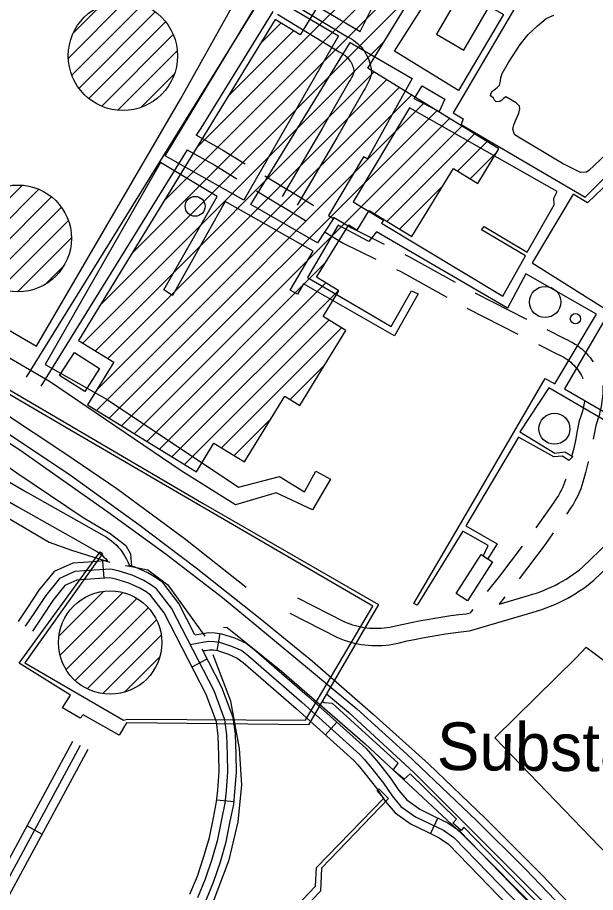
# Model space of a CAD drawing. Extents: x 3568792 to 3606828, y 529143 to 554785.
# Drawn here: x 3577651 to 3578658, y 544184 to 545708 of the extents above; entities that cross this region are included whole.
import ezdxf

# ---------------------------------------------------------------- set-up
doc = ezdxf.new("R2010")
doc.units = 0
for name, color, linetype in [('V-BLDG-OTLN', 7, 'Continuous'), ('V-DOMW-TANK', 7, 'Continuous'), ('V-RAIL-TRAK', 7, 'Continuous'), ('V-ROAD-CNTR', 7, 'Continuous'), ('V-SITE-OTLN', 7, 'Continuous'), ('V-SITE-OTLN-IDEN', 7, 'Continuous'), ('V-TOPO-SHOR', 7, 'Continuous'), ('V-UTIL-LINE', 7, 'Continuous')]:
    doc.layers.add(name, color=color, linetype=linetype)

msp = doc.modelspace()

# ---------------------------------------------------------------- linework, layer by layer
at = {"layer": 'V-BLDG-OTLN'}
for points in [[(3578100.3, 545703.9), (3577757.5, 545145.3), (3577819.1, 545107.6), (3577773.2, 545032.8), (3577962.9, 544916.4), (3577993.6, 544966.4), (3578047, 544933.6), (3578117.2, 545048), (3578143, 545032.1), (3578223.2, 545162.7), (3578183.8, 545186.8), (3578211.4, 545231.7), (3578172.5, 545255.6), (3578228.4, 545346.6), (3578243.2, 545337.5), (3578264, 545371.5), (3578338.1, 545326.1), (3578410.9, 545444.6), (3578453.3, 545418.6), (3578490.2, 545478.8), (3578261.4, 545619.2), (3578452.2, 545930.2), (3578340.8, 545998.6), (3578143.7, 545677.3)], [(3578479.1, 545846.8), (3578381.5, 545678.6), (3578429.2, 545650.9), (3578526.8, 545819.1)], [(3577750.3, 545124.4), (3577794.2, 545096.6), (3577768.6, 545056.2), (3577724.7, 545084)], [(3578478.9, 544759.6), (3578435.2, 544691.8), (3578415.8, 544704.3), (3578459.4, 544772.1)]]:
    msp.add_lwpolyline(points, close=True, dxfattribs=at)
for points in [[(3577962.8, 545479.9), (3578428, 545945.1)], [(3577906.7, 545388.4), (3578449.9, 545931.6)], [(3577850.5, 545296.9), (3578402.2, 545848.6)], [(3577794.4, 545205.4), (3578346, 545757.1)], [(3578075.1, 545662.9), (3578110.1, 545697.9)], [(3578018.9, 545571.4), (3578132, 545684.4)], [(3577765.1, 545140.7), (3578289.9, 545665.6)], [(3577787, 545127.3), (3578272.3, 545612.6)], [(3577808.9, 545113.8), (3578294.2, 545599.1)], [(3577789, 545058.6), (3578316.1, 545585.7)], [(3577788.9, 545023.2), (3578338, 545572.2)], [(3577810.8, 545009.7), (3578359.9, 545558.8)], [(3577832.7, 544996.3), (3578381.8, 545545.3)], [(3577854.7, 544982.8), (3578403.7, 545531.9)], [(3578273.1, 545365.9), (3578425.6, 545518.5)], [(3578295, 545352.5), (3578447.5, 545505)], [(3578418.1, 545440.2), (3578469.5, 545491.6)], [(3578440, 545426.8), (3578487.4, 545474.1)], [(3578316.9, 545339.1), (3578392.5, 545414.6)], [(3577876.6, 544969.4), (3578188.1, 545280.9)], [(3577898.5, 544956), (3578188.4, 545245.8)], [(3577920.4, 544942.5), (3578210.3, 545232.4)], [(3577942.3, 544929.1), (3578193.9, 545180.6)], [(3578006.8, 544958.2), (3578215.8, 545167.2)], [(3578126.3, 545042.4), (3578185.9, 545102)], [(3578028.7, 544944.8), (3578093.7, 545009.8)]]:
    msp.add_lwpolyline(points, dxfattribs=at)
at = {"layer": 'V-DOMW-TANK'}
for p, q in [((3577740.1, 545636.9), (3577839.1, 545735.9)), ((3577746, 545607.5), (3577868.4, 545729.8)), ((3577748.6, 545680.8), (3577794.8, 545727)), ((3577758.5, 545584.6), (3577891.3, 545717.4)), ((3577775.8, 545566.5), (3577909.4, 545700.1)), ((3577797.9, 545553.3), (3577922.5, 545677.9)), ((3577826.2, 545546.3), (3577929.7, 545649.7)), ((3577866.6, 545551.3), (3577924.7, 545609.4)), ((3577559.6, 545315), (3577660.1, 545415.5)), ((3577566.7, 545286.7), (3577688.5, 545408.5)), ((3577579.8, 545264.5), (3577710.6, 545395.3)), ((3577598.1, 545247.4), (3577727.6, 545377)), ((3577621.4, 545235.4), (3577739.7, 545353.7)), ((3577651.4, 545230), (3577745.1, 545323.8)), ((3577700.2, 545243.5), (3577731.8, 545275.1)), ((3577723.7, 544630.6), (3577801.2, 544708.1)), ((3577725.6, 544597.1), (3577834.5, 544706)), ((3577736, 544572.2), (3577859.4, 544695.6)), ((3577751.9, 544552.7), (3577878.9, 544679.7)), ((3577772.9, 544538.3), (3577893.2, 544658.7)), ((3577799.9, 544530), (3577901.6, 544631.7)), ((3577837.9, 544532.6), (3577898.8, 544593.6))]:
    msp.add_line(p, q, dxfattribs=at)
for centre, radius in [((3577834.9, 545640.9), 95.2), ((3577652.2, 545322.9), 93), ((3577960.7, 545378.8), 17.3), ((3578570.6, 545212.1), 27.2), ((3578623.4, 545183.1), 8.92), ((3578586.9, 544991.3), 27), ((3577812.7, 544619), 90)]:
    msp.add_circle(centre, radius, dxfattribs=at)
at = {"layer": 'V-RAIL-TRAK'}
for points in [[(3576442.5, 545653.1), (3576566.5, 545591.5), (3576666.9, 545539.9), (3576763.3, 545491), (3576857.8, 545440.8), (3576956.5, 545388.7), (3577025.7, 545352.9), (3577107.2, 545310.4), (3577213, 545254.2), (3577307.1, 545203.1), (3577446, 545125.3), (3577537.4, 545075.5), (3577625.1, 545020.7), (3577733.7, 544948.8), (3577824.2, 544887.2), (3577944.1, 544799), (3578049.9, 544715.7)], [(3576949.8, 545377.1), (3577053.4, 545322.8), (3577102.6, 545296.8), (3577193.7, 545248.6), (3577322.1, 545177.5), (3577447, 545102.9), (3577541.1, 545044.9), (3577633.4, 544984.3), (3577743.3, 544910.5), (3577862.7, 544824.6), (3577962.7, 544749.4), (3578074, 544660.7), (3578165.3, 544586.5), (3578271.2, 544494.2), (3578367.5, 544407.8), (3578466.6, 544312.8), (3578565.7, 544214.1), (3578656.6, 544118.2)], [(3577102.6, 545296.8), (3577189.6, 545239), (3577285.8, 545181.3), (3577366.5, 545134.1), (3577454.4, 545082.3), (3577555.7, 545018.6), (3577655.5, 544954.4), (3577808.5, 544846.7), (3577910.2, 544773), (3578008.7, 544697.3), (3578071.9, 544645.1), (3578159.9, 544572.2), (3578242.4, 544503.5), (3578329.8, 544424.7), (3578451.2, 544308.8), (3578536.4, 544224.4), (3578627.1, 544129.6)]]:
    msp.add_lwpolyline(points, dxfattribs=at)
at = {"layer": 'V-ROAD-CNTR'}
for p, q in [((3577802.4, 544731.1), (3577800, 544761)), ((3578500.5, 544698.4), (3578490.4, 544685.9)), ((3578444.4, 544676.6), (3578439.8, 544671)), ((3578004, 544634.6), (3577998.7, 544605)), ((3577955.3, 544576.7), (3577981.9, 544590.4)), ((3578207.6, 544480.3), (3578187.5, 544458)), ((3577998.6, 544345), (3578028.4, 544341.9)), ((3578383.6, 544313.5), (3578370.7, 544286.4)), ((3577667.8, 544299.7), (3577694.2, 544285.5))]:
    msp.add_line(p, q, dxfattribs=at)
for points in [[(3578119.5, 545738.8), (3578226.4, 545674.1), (3578229.3, 545672.6), (3578233.1, 545670.4), (3578236.8, 545668), (3578240.3, 545665.4), (3578243.6, 545662.5), (3578246.8, 545659.5), (3578249.8, 545656.3), (3578252.5, 545652.9), (3578255.1, 545649.4), (3578257.5, 545645.7), (3578259.6, 545641.9), (3578261.5, 545638), (3578263.2, 545633.9), (3578264.6, 545629.8), (3578265.8, 545625.6), (3578266.7, 545621.3), (3578267.4, 545617), (3578268, 545610.1), (3578265.8, 545602.8), (3578264, 545597.9), (3578261.9, 545593.2), (3578259.6, 545588.6), (3578257, 545584.2), (3578254.7, 545580.6), (3578207.5, 545498), (3578138.3, 545380.7)], [(3577667.2, 545081.4), (3577945.5, 545531), (3578071.4, 545733.9)], [(3577963.1, 545502.5), (3577971, 545515.2), (3578096.9, 545718)], [(3578104, 545713.2), (3578211.9, 545647.8), (3578215.1, 545646.1), (3578217.4, 545644.9), (3578219.5, 545643.4), (3578221.6, 545641.9), (3578223.6, 545640.2), (3578225.4, 545638.4), (3578227.2, 545636.5), (3578228.8, 545634.5), (3578230.4, 545632.4), (3578231.8, 545630.3), (3578233, 545628), (3578234.1, 545625.7), (3578235.1, 545623.3), (3578236, 545620.9), (3578236.7, 545618.4), (3578237.2, 545615.9), (3578237.6, 545613.3), (3578237.6, 545613.3), (3578237.4, 545612.4), (3578236.2, 545609.2), (3578234.8, 545606), (3578233.2, 545602.9), (3578231.5, 545599.9), (3578229.1, 545596.3), (3578181.5, 545513.1), (3578112.5, 545396)], [(3577961.7, 545503.4), (3578010, 545476.3), (3578048.1, 545453)], [(3577692.7, 545065.6), (3577947.5, 545477.4)], [(3577947, 545477.2), (3577994.8, 545450.4), (3578033.4, 545426.8)], [(3578082.2, 545432.1), (3578114.5, 545412.4), (3578133.1, 545401.2), (3578167.8, 545380.4)], [(3578067.5, 545405.9), (3578099, 545386.7), (3578117.7, 545375.5), (3578153.1, 545354.2)], [(3578202.1, 545359.9), (3578233.3, 545341.1), (3578290.3, 545312.8)], [(3578187.4, 545333.7), (3578218.9, 545314.8), (3578275.6, 545286.6)], [(3578326.1, 545295), (3578332.9, 545291.6), (3578413.7, 545246.8)], [(3578311.4, 545268.8), (3578318.9, 545265), (3578399.1, 545220.7)], [(3578448.7, 545227.5), (3578449.1, 545227.3), (3578538, 545182.4)], [(3578434.1, 545201.3), (3578435.1, 545200.7), (3578523.3, 545156.2)], [(3578573.7, 545164.3), (3578605.3, 545148.2), (3578609.3, 545146.5), (3578613.9, 545144.2), (3578618.3, 545141.7), (3578622.7, 545139), (3578626.9, 545136.1), (3578631, 545133.1), (3578634.9, 545129.8), (3578638.7, 545126.4), (3578642.3, 545122.8), (3578645.7, 545119.1), (3578649, 545115.2), (3578652.1, 545111.1), (3578654.4, 545107.8)], [(3578559, 545138.1), (3578592.4, 545121.1), (3578596.5, 545119.3), (3578599.9, 545117.6), (3578603.1, 545115.8), (3578606.3, 545113.9), (3578609.4, 545111.8), (3578612.4, 545109.5), (3578615.3, 545107.1), (3578618, 545104.6), (3578620.7, 545102), (3578623.2, 545099.3), (3578625.6, 545096.4), (3578627.9, 545093.4), (3578630, 545090.4), (3578632, 545087.2), (3578633.8, 545083.9), (3578635.5, 545080.6), (3578636.4, 545078.8)], [(3578671.3, 545066.9), (3578671.2, 545059.8), (3578670.9, 545053.3), (3578670.4, 545046.7), (3578669.6, 545040.2), (3578668.7, 545033.7), (3578667.5, 545027.3), (3578666.1, 545020.9), (3578664.5, 545014.5), (3578662.7, 545008.2), (3578660.7, 545002), (3578658.9, 544997.2), (3578656.1, 544981.7), (3578654.4, 544973.4)], [(3578639.3, 545039.8), (3578639.1, 545038.6), (3578638.1, 545033.1), (3578636.9, 545027.7), (3578635.6, 545022.3), (3578634, 545017), (3578632.3, 545011.7), (3578629.9, 545005.1), (3578626.6, 544987.5), (3578623.3, 544971.2), (3578619.8, 544955), (3578616.8, 544942.4)], [(3578645.7, 544934.4), (3578645.1, 544931.7), (3578641, 544915.2), (3578636.5, 544898.5), (3578634.6, 544892.7), (3578632.6, 544887), (3578630.3, 544881.3), (3578627.9, 544875.8), (3578625.2, 544870.3), (3578622.4, 544865), (3578619.3, 544859.7), (3578616.1, 544854.6), (3578612.7, 544849.6), (3578609.4, 544845.1), (3578607.8, 544842.8)], [(3577603.2, 544918.2), (3577666.6, 544881.5), (3577758.2, 544830), (3577806.6, 544802.3), (3577811.1, 544799.3), (3577815.2, 544796.1), (3577819.2, 544792.8), (3577823, 544789.2), (3577826.6, 544785.4), (3577830, 544781.5), (3577833.2, 544777.4), (3577836.2, 544773.1), (3577838.9, 544768.6), (3577841.4, 544764.1), (3577843.7, 544759.4), (3577845.7, 544754.6), (3577846.1, 544753.6)], [(3578606.7, 544903.8), (3578606.2, 544902.2), (3578604.5, 544897.6), (3578602.7, 544892.9), (3578600.7, 544888.4), (3578598.5, 544883.9), (3578596.2, 544879.5), (3578593.7, 544875.2), (3578591, 544871), (3578588.2, 544866.9), (3578585, 544862.6), (3578554.5, 544819)], [(3577587.6, 544892.6), (3577651.8, 544855.5), (3577743.4, 544803.9), (3577790.7, 544776.9), (3577793.5, 544774.9), (3577796.4, 544772.7), (3577799.2, 544770.4), (3577801.9, 544767.9), (3577804.4, 544765.2), (3577806.8, 544762.5), (3577807.5, 544761.6)], [(3578584.9, 544810.1), (3578570.8, 544790), (3578525.2, 544729.8)], [(3578490.4, 544685.9), (3578541.6, 544701), (3578548.7, 544703), (3578555.5, 544705.2), (3578562.2, 544707.6), (3578568.9, 544710.2), (3578575.5, 544713), (3578582, 544715.9), (3578588.4, 544719.1), (3578594.7, 544722.4), (3578600.9, 544725.9), (3578607.1, 544729.6), (3578613.1, 544733.4), (3578619, 544737.4), (3578624.8, 544741.6), (3578630.5, 544745.9), (3578635.7, 544750.2), (3578680.3, 544793)], [(3578530.8, 544786.8), (3578491.3, 544734.7), (3578469.5, 544707.8)], [(3577808.6, 544761.7), (3577783.8, 544759.8), (3577747.5, 544757.3), (3577714.9, 544742.7), (3577688.7, 544710.1), (3577668.5, 544680), (3577652.3, 544655.6)], [(3578125.7, 544670.1), (3578208.7, 544627.9), (3578214.7, 544625.4), (3578220.4, 544623.3), (3578226.2, 544621.4), (3578232.1, 544619.7), (3578238.1, 544618.2), (3578244, 544616.9), (3578250.1, 544615.8), (3578256.2, 544615), (3578262.2, 544614.4), (3578268.4, 544614), (3578274.5, 544613.8), (3578280.6, 544613.8), (3578286.7, 544614.1), (3578292.8, 544614.6), (3578298.9, 544615.3), (3578305, 544616.2), (3578311, 544617.4), (3578316.7, 544618.7), (3578330.1, 544621.8), (3578346.1, 544625.2), (3578356.8, 544627.3), (3578370.2, 544629.8), (3578383.6, 544632.1), (3578397, 544634.2), (3578410.5, 544636.1), (3578424, 544637.8), (3578438.9, 544639.5), (3578452.7, 544643.5), (3578550, 544672.2), (3578557.5, 544674.3), (3578565.1, 544676.8), (3578572.6, 544679.5), (3578580.1, 544682.4), (3578587.5, 544685.5), (3578594.8, 544688.8), (3578601.9, 544692.3), (3578609, 544696), (3578616, 544699.9), (3578622.9, 544704), (3578629.6, 544708.4), (3578636.2, 544712.8), (3578642.7, 544717.5), (3578649, 544722.4), (3578655.6, 544727.7), (3578701.2, 544771.5)], [(3577965.5, 544174.9), (3577978.7, 544207.2), (3577990.4, 544241.7), (3578000.3, 544275.8), (3578007.3, 544310.6), (3578013.1, 544339.4), (3578015.3, 544360.6), (3578017.7, 544393.9), (3578017.3, 544423.4), (3578015.9, 544458.1), (3578012.4, 544484.7), (3577993.7, 544534.8), (3577919.4, 544679.1), (3577893.6, 544712.6), (3577883.6, 544719.8), (3577871.2, 544727), (3577850.8, 544736.3), (3577826.7, 544744.1), (3577813, 544747), (3577784.9, 544744.8), (3577751.2, 544742.5), (3577724.4, 544730.5), (3577700.8, 544701.2), (3577681, 544671.6), (3577664.7, 544647.3)], [(3577960.4, 544632.2), (3577932.1, 544687.2), (3577904.2, 544723.5), (3577891.7, 544732.4), (3577878.1, 544740.4), (3577856.2, 544750.3), (3577845.3, 544753.8)], [(3577951.8, 544180.9), (3577964.6, 544212.4), (3577976.1, 544246.2), (3577985.7, 544279.3), (3577992.6, 544313.6), (3577998.2, 544341.7), (3578000.4, 544361.9), (3578002.7, 544394.4), (3578002.3, 544423), (3578001, 544456.8), (3577997.7, 544481.1), (3577979.9, 544528.8), (3577906.7, 544671), (3577883.1, 544701.7), (3577875.4, 544707.2), (3577864.3, 544713.6), (3577845.4, 544722.3), (3577822.8, 544729.6), (3577812, 544731.9), (3577786, 544729.8), (3577754.9, 544727.7), (3577733.8, 544718.3), (3577712.9, 544692.3), (3577693.4, 544663.3), (3577677.2, 544639)], [(3578139.3, 544696.8), (3578221.2, 544655.1), (3578225.6, 544653.3), (3578230.3, 544651.6), (3578235.1, 544650), (3578239.9, 544648.6), (3578244.8, 544647.4), (3578249.8, 544646.3), (3578254.7, 544645.5), (3578259.7, 544644.8), (3578264.7, 544644.3), (3578269.8, 544643.9), (3578274.8, 544643.8), (3578279.9, 544643.8), (3578284.9, 544644), (3578289.9, 544644.4), (3578294.9, 544645), (3578299.9, 544645.8), (3578304.9, 544646.7), (3578310, 544647.9), (3578323.6, 544651.1), (3578340, 544654.6), (3578351.1, 544656.8), (3578364.9, 544659.4), (3578378.7, 544661.7), (3578392.6, 544663.9), (3578406.5, 544665.9), (3578420.5, 544667.6), (3578433, 544669), (3578439.9, 544671)], [(3577960.8, 544632.7), (3577974, 544635), (3577983.9, 544636.4), (3577995.6, 544636.1), (3578006.6, 544634.1), (3578029.6, 544627.1), (3578049.6, 544618.1), (3578063.3, 544607.7), (3578156.5, 544526.3), (3578258, 544434.8), (3578266.4, 544425.9), (3578280.5, 544409.3), (3578300.9, 544383), (3578315.8, 544361.1), (3578329.6, 544344.8), (3578352.4, 544328.6), (3578377.8, 544316.3), (3578401.2, 544305.1), (3578421.6, 544291), (3578600.8, 544106.1), (3578664.7, 544019.3)], [(3577951.9, 544615.9), (3577976.3, 544620.2), (3577984.7, 544621.3), (3577994.1, 544621.1), (3578003.1, 544619.5), (3578024.3, 544613), (3578041.9, 544605.1), (3578053.9, 544596), (3578146.6, 544515.1), (3578247.5, 544424.1), (3578255.2, 544415.9), (3578268.8, 544399.8), (3578288.7, 544374.1), (3578303.9, 544352), (3578319.4, 544333.7), (3578344.7, 544315.6), (3578371.3, 544302.8), (3578393.6, 544292.1), (3578411.8, 544279.5), (3578589.3, 544096.4), (3578652.6, 544010.4)], [(3577796, 543851.1), (3577813.3, 543867.9), (3577827.7, 543886.7), (3577843.4, 543908.7), (3577883.1, 543969.8), (3577911.2, 544025.3), (3577961.4, 544130.1), (3577979.3, 544169), (3577992.8, 544201.9), (3578004.7, 544237.2), (3578014.9, 544272.2), (3578022, 544307.7), (3578027.9, 544337.1), (3578030.2, 544359.2), (3578032.7, 544393.5), (3578032.3, 544423.8), (3578030.9, 544459.4), (3578027, 544488.4), (3578007.4, 544540.9), (3577973.2, 544607.4)], [(3577975.8, 544604.9), (3577978.6, 544605.3), (3577985.6, 544606.3), (3577992.6, 544606.2), (3577999.5, 544604.9), (3578019, 544599), (3578034.2, 544592.1), (3578044.4, 544584.4), (3578136.6, 544503.9), (3578237, 544413.4), (3578244, 544405.9), (3578257.1, 544390.4), (3578276.6, 544365.3), (3578291.9, 544342.9), (3578309.1, 544322.6), (3578337, 544302.7), (3578364.8, 544289.3), (3578386.1, 544279.1), (3578402.1, 544268), (3578577.9, 544086.6), (3578630.8, 544014.8)], [(3576880.6, 542873.3), (3576897.4, 542894), (3576916.9, 542921.6), (3577159.8, 543354.8), (3577380.1, 543731.5), (3577386.9, 543744.7), (3577391.9, 543755), (3577399.8, 543775.1), (3577466.1, 543997.9), (3577473.5, 544013.4), (3577487, 544044.8), (3577508.6, 544072), (3577524.9, 544083.5), (3577542.7, 544093.1), (3577556, 544101.8), (3577569, 544117.2), (3577747.7, 544447.5)], [(3576792.6, 542747.3), (3576849.8, 542817.2), (3576876.2, 542843.7), (3576886.7, 542857.1), (3576909.3, 542884.9), (3576929.6, 542913.6), (3577172.8, 543347.3), (3577393.2, 543724.2), (3577400.3, 543738), (3577405.7, 543748.9), (3577414, 543770.3), (3577480.1, 543992.4), (3577487.2, 544007.2), (3577500, 544037), (3577519, 544061), (3577532.8, 544070.8), (3577550.4, 544080.1), (3577566, 544090.4), (3577581.5, 544108.7), (3577760.9, 544440.3)], [(3577575, 544078.4), (3577576.1, 544079.1), (3577593.9, 544100.1), (3577774.1, 544433.2)]]:
    msp.add_lwpolyline(points, dxfattribs=at)
at = {"layer": 'V-SITE-OTLN'}
msp.add_lwpolyline([(3578483, 544453.3), (3578625.1, 544593), (3578642.2, 544611), (3578669.7, 544589.8), (3578739.2, 544519.9), (3578816.4, 544439), (3578818.2, 544431.6), (3578814.5, 544396.2), (3578810.4, 544386.6), (3578804.4, 544377.4), (3578770.9, 544337.8), (3578679.8, 544248.7)], close=True, dxfattribs=at)
at = {"layer": 'V-TOPO-SHOR'}
for points in [[(3578685.3, 545476.9), (3578646.6, 545441), (3578642.6, 545438.3), (3578632.2, 545437.8), (3578625.5, 545441), (3578600.8, 545453.1), (3578521.2, 545500.8), (3578517.1, 545503.9), (3578514.4, 545512.9), (3578516.2, 545520.6), (3578520.7, 545531.8), (3578524.8, 545540.8), (3578526.6, 545548.5), (3578525.7, 545553), (3578520.3, 545558.8), (3578502.3, 545569.2), (3578497.8, 545566.5), (3578495.1, 545563.8), (3578491.5, 545561.1), (3578485.2, 545560.6), (3578482.5, 545563.8), (3578480.7, 545567.4), (3578476.6, 545570.5), (3578475.7, 545572.3), (3578478, 545578.6), (3578481.1, 545581.3), (3578487.4, 545586.3), (3578491, 545589.9), (3578492.8, 545596.6), (3578493.7, 545603.3), (3578496, 545610.1), (3578506.8, 545629.4), (3578527, 545660.9), (3578541, 545678), (3578557.2, 545693.3), (3578572.5, 545705.9), (3578586, 545711.7)], [(3577458, 545041.9), (3577563.7, 544974.8), (3577650.1, 544914.5), (3577765.5, 544836.8), (3577812.9, 544809.2), (3577840, 544788), (3577848.3, 544773.8), (3577849.9, 544751.2)], [(3577377.3, 544986.9), (3577553.2, 544883.8), (3577706.2, 544794), (3577745.1, 544779.8), (3577812, 544759.2)], [(3577839.5, 544753.2), (3577849.9, 544751.2), (3577878.5, 544745.9), (3577913.3, 544719.7), (3577977.9, 544630.4)], [(3578010.4, 544646), (3578016.8, 544645.5), (3578111.2, 544569.4), (3578256.8, 544442.5), (3578425, 544286.2), (3578572.9, 544137.8), (3578734.2, 543956.8), (3578869.3, 543799.1), (3579043.8, 543571.4), (3579164.7, 543401.4), (3579287, 543209.4), (3579313.6, 543161.3), (3579319.1, 543159.5)], [(3577818.7, 543826.7), (3577882.4, 543936.2), (3577936.4, 544037.9), (3577980.4, 544135.9), (3578020.3, 544240.4), (3578035.9, 544306.8), (3578042.3, 544371.4), (3578038.2, 544434.2), (3578022.7, 544517.1), (3577992, 544597.7)]]:
    msp.add_lwpolyline(points, dxfattribs=at)
at = {"layer": 'V-UTIL-LINE'}
msp.add_line((3577836, 544483.9), (3577842.8, 544485.7), dxfattribs=at)
for points in [[(3578481, 545957.2), (3578599.5, 545888.4), (3578504.7, 545725.8), (3578483.3, 545736.3), (3578478.7, 545724), (3578498.3, 545712.6), (3578419.5, 545580.5), (3578307.9, 545648.9), (3578359.4, 545729), (3578349.3, 545734.9), (3578481, 545957.2)], [(3576463, 545507.9), (3576471.7, 545523.6), (3576592.1, 545455.1), (3576685.9, 545624.6), (3576953.8, 545493.3), (3576972.9, 545517.9), (3577067.7, 545465.1), (3577103.2, 545468.7), (3577401.1, 545300.1), (3577684.4, 545135.2), (3577935, 545565.2), (3578062.6, 545793.8), (3578248.5, 545683.5), (3578288.6, 545763.7)], [(3578081.3, 545752.4), (3578210.7, 545675.8), (3578045.7, 545389.7), (3577908.6, 545466.8), (3578081.3, 545752.4)], [(3578534.6, 545753.6), (3578410.6, 545541.4)], [(3578230.8, 545664.4), (3578338.8, 545601.5), (3578261.3, 545461.7), (3578254, 545464.9), (3578192.9, 545362.8), (3578201.6, 545357.8), (3578173.8, 545315), (3578057.6, 545382), (3578230.8, 545664.4)], [(3578342.4, 545565.8), (3578356.5, 545588.6), (3578396.1, 545565.4), (3578385.7, 545544), (3578342.4, 545565.8)], [(3578334.3, 545550.2), (3578236.4, 545386.7), (3578288.7, 545354.4), (3578285.6, 545349.3), (3578496.9, 545222.2), (3578536.6, 545292.8), (3578460, 545337.9), (3578464.1, 545343.8), (3578539.3, 545299.2), (3578586.2, 545381.2), (3578585.8, 545393), (3578591.7, 545404.4), (3578334.3, 545550.2)], [(3578410.6, 545541.4), (3578427.9, 545531.4), (3578424.3, 545521.3), (3578640.2, 545394.7), (3578708.5, 545463.4)], [(3578730.3, 544973.3), (3578576.8, 545062.6), (3578526.7, 544986.1), (3578587.3, 544948.7), (3578605, 544951), (3578618.7, 544942.8), (3578611.9, 544935.9), (3578600.9, 544943.7), (3578585.5, 544942.3), (3578524, 544976.9), (3578432.4, 544822.5), (3578487, 544791.1), (3578470.2, 544764.2), (3578462.4, 544769.7), (3578471.5, 544787.9), (3578427.4, 544813), (3578347.6, 544684.1), (3578342.1, 544687.2), (3578425.1, 544828.9), (3578570.4, 545079), (3578587.8, 545069.4), (3578660.2, 545191), (3578537.2, 545261.2), (3578504.9, 545201.5), (3578276.7, 545334.6), (3578263.4, 545317.3), (3578210.2, 545346), (3578156.8, 545254.9), (3578252.9, 545198.4), (3578302.6, 545169.2), (3578337.7, 545231.6), (3578349.1, 545226.2), (3578308.1, 545153.3), (3578149.5, 545244), (3578139.1, 545225.7), (3578126.3, 545233), (3578166.4, 545300.9), (3578012.9, 545387), (3577921.3, 545223.5), (3577906.3, 545233.1), (3577999.2, 545395.7), (3577900.4, 545455.4), (3577699.4, 545103.3), (3577807.4, 545042.2), (3578036.1, 544889.6), (3578107.6, 544908.2), (3578151.3, 544881.3), (3578170.9, 544917.3), (3578196.4, 544903.7), (3578165.4, 544849.9), (3578102.1, 544880), (3578031, 544858.6), (3577936.7, 544918.3), (3577707.2, 545073.7), (3577452.5, 545221.8)], [(3578711.3, 545448.9), (3578644.3, 545384.6), (3578619.2, 545399.7), (3578548.2, 545280.3), (3578682.5, 545195.6), (3578604.2, 545060.7), (3578739.4, 544982.8)], [(3577842.8, 544485.7), (3578153, 544483.9), (3578270.1, 544682.5), (3577742.7, 544989.6), (3577494, 545134.5), (3577499, 545140), (3577974.5, 544861.1), (3578280.2, 544685.2), (3578158.5, 544475.7), (3577841.4, 544479.4), (3577828.2, 544457.5), (3577765.8, 544493.1), (3577760.3, 544487.1), (3577729.4, 544505.4), (3577743.5, 544527.2)], [(3577743.5, 544527.2), (3577654.2, 544583.3), (3577795, 544776.9), (3577799.1, 544774.1), (3577664.2, 544583.7), (3577836, 544483.9)], [(3578189.8, 544529.6), (3578228.2, 544498), (3578342.1, 544392.7), (3578565.7, 544169), (3578775.2, 543941.2), (3579032.6, 543621.3), (3579232.5, 543334.8), (3579413.3, 543045.5), (3579475.7, 542932.5), (3579407.8, 542897), (3579483.4, 542752.5), (3579643.2, 542441.4), (3579761.6, 542177.1)], [(3578625.4, 544095.2), (3578429.1, 544297.5), (3578424.1, 544291.6), (3578409.5, 544304.3), (3578416.3, 544311.2), (3578335.2, 544390.4), (3578325.2, 544380.9), (3578306.1, 544396.8), (3578314.3, 544408.7), (3578200, 544513), (3578185.4, 544513.9), (3578182.2, 544516.5)], [(3578280.6, 544364.5), (3578297.4, 544347.2), (3578180.8, 544226), (3578179.4, 544185.9), (3578055.9, 544058.4), (3578017.2, 544018.8), (3577932, 543876.2), (3577872.3, 543779.2), (3577879.1, 543774.2), (3577876.4, 543767.8), (3577860.5, 543778.7), (3577959.3, 543941.3), (3578013.6, 544033.3), (3578066.9, 544088.9), (3578070.1, 544088.9), (3578170.3, 544195), (3578172.1, 544227.4), (3578289.7, 544348.1), (3578277.8, 544361.3), (3578280.6, 544364.5)]]:
    msp.add_lwpolyline(points, dxfattribs=at)

# ---------------------------------------------------------------- texts
at = {"layer": 'V-SITE-OTLN-IDEN'}
msp.add_text('Substation', height=83, rotation=359.5143, dxfattribs=at).set_placement((3578381.8, 544397.2))

doc.saveas('drawing.dxf')
